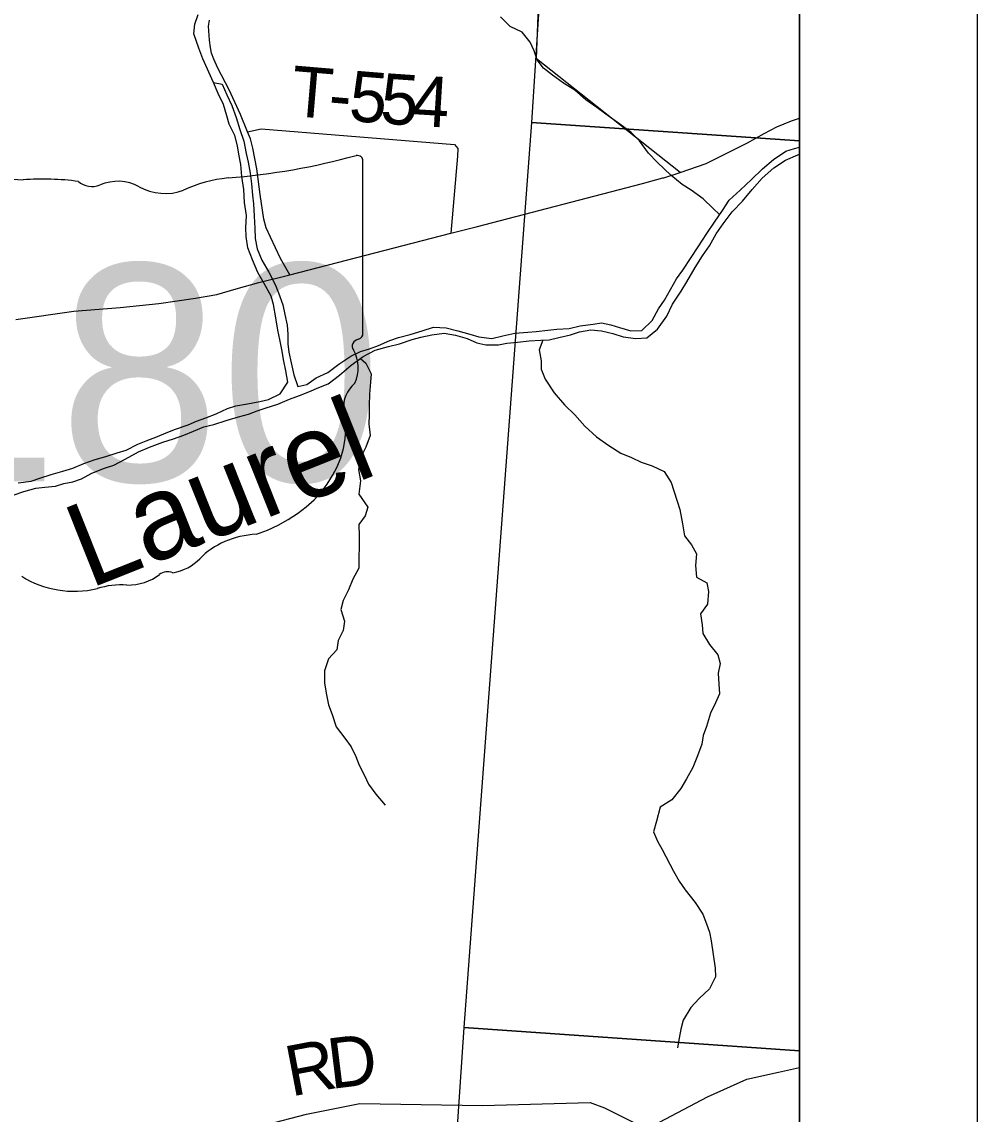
# Model space of a CAD drawing. Extents: x 0 to 42.5, y 0 to 22.
# Drawn here: x 8.462 to 9, y 16.014 to 16.629 of the extents above; entities that cross this region are included whole.
import ezdxf

# ---------------------------------------------------------------- set-up
doc = ezdxf.new("R2010")
doc.units = 0
for name, color, linetype in [('GM_X_County_Road', 7, 'Continuous'), ('GM_X_County_Road_Text', 7, 'Continuous'), ('GM_X_Interchange_Ramps', 7, 'Continuous'), ('GM_X_Minor_River', 7, 'Continuous'), ('GM_X_Minor_River_Text', 7, 'Continuous'), ('GM_X_State_Location', 7, 'Continuous'), ('GM_X_State_Route', 7, 'Continuous'), ('GM_X_State_Shield', 7, 'Continuous'), ('GM_X_Township_Road', 7, 'Continuous'), ('GM_X_Township_Road_Text', 7, 'Continuous'), ('GM_X_Unincorporated', 7, 'Continuous'), ('SH_Cut_Line', 7, 'Continuous'), ('SH_Data', 7, 'Continuous')]:
    doc.layers.add(name, color=color, linetype=linetype)

msp = doc.modelspace()

# ---------------------------------------------------------------- linework, layer by layer
at = {"layer": 'GM_X_County_Road'}
for points in [[(8.82122, 16.00948), (8.84828, 16.02374), (8.87043, 16.03379), (8.88825, 16.03773), (8.9, 16.04036)], [(8.59942, 16.00794), (8.62254, 16.01401), (8.65251, 16.01994), (8.72145, 16.01896), (8.78221, 16.02057), (8.79021, 16.01759), (8.80679, 16.00936)]]:
    msp.add_lwpolyline(points, dxfattribs=at)
at = {"layer": 'GM_X_Interchange_Ramps'}
msp.add_lwpolyline([(8.9, 15.53758), (8.9, 19.05381), (8.80207, 19.06082), (8.79715, 19.06117), (8.45529, 19.08562), (8.42249, 18.59682), (8.4216, 18.58362), (8.41233, 18.47844), (8.38323, 18.14846), (8.33786, 17.63394), (8.30797, 17.29222), (8.30866, 17.28459), (8.30841, 17.27648), (8.30737, 17.26941), (8.29023, 17.08765), (8.28773, 17.0646), (8.28228, 16.99116), (8.27401, 16.89234), (8.25723, 16.70556), (8.24802, 16.59431), (8.24781, 16.59008), (8.17933, 15.79111)], dxfattribs=at)
at = {"layer": 'GM_X_Minor_River'}
for p, q in [((8.5595, 16.62791), (8.56143, 16.63339)), ((8.7371, 16.62657), (8.73165, 16.6321)), ((8.55908, 16.62241), (8.5595, 16.62791)), ((8.74389, 16.62349), (8.7371, 16.62657)), ((8.56186, 16.61443), (8.55908, 16.62241)), ((8.74839, 16.61777), (8.74389, 16.62349)), ((8.56409, 16.60834), (8.56186, 16.61443)), ((8.75063, 16.61301), (8.74839, 16.61777)), ((8.7523, 16.60788), (8.75063, 16.61301)), ((8.57005, 16.59503), (8.56409, 16.60834)), ((8.75586, 16.60312), (8.7523, 16.60788)), ((8.76095, 16.59929), (8.75586, 16.60312)), ((8.76716, 16.5947), (8.76095, 16.59929)), ((8.77357, 16.59068), (8.76716, 16.5947)), ((8.77978, 16.58533), (8.77357, 16.59068)), ((8.78581, 16.58093), (8.77978, 16.58533)), ((8.79089, 16.57729), (8.78581, 16.58093)), ((8.7988, 16.57155), (8.79089, 16.57729)), ((8.80521, 16.56696), (8.7988, 16.57155)), ((8.80991, 16.56219), (8.80521, 16.56696)), ((8.81497, 16.55533), (8.80991, 16.56219)), ((8.82004, 16.54998), (8.81497, 16.55533)), ((8.82757, 16.54292), (8.82004, 16.54998)), ((8.83396, 16.53757), (8.82757, 16.54292)), ((8.83905, 16.5345), (8.83396, 16.53757)), ((8.84584, 16.52952), (8.83905, 16.5345)), ((8.85148, 16.52418), (8.84584, 16.52952)), ((8.85504, 16.52069), (8.85148, 16.52418)), ((8.75555, 16.44994), (8.75339, 16.44459)), ((8.75339, 16.44459), (8.75448, 16.43833)), ((8.6529, 16.43963), (8.65582, 16.43707)), ((8.65582, 16.43707), (8.6588, 16.43098)), ((8.75448, 16.43833), (8.75463, 16.43359)), ((8.6588, 16.43098), (8.65839, 16.42625)), ((8.75463, 16.43359), (8.75686, 16.42807)), ((8.75686, 16.42807), (8.76192, 16.42027)), ((8.65839, 16.42625), (8.65796, 16.41961)), ((8.65796, 16.41961), (8.65773, 16.41316)), ((8.76192, 16.42027), (8.76774, 16.41359)), ((8.65773, 16.41316), (8.65769, 16.40785)), ((8.76774, 16.41359), (8.77357, 16.40786)), ((8.65769, 16.40785), (8.65746, 16.40274)), ((8.77357, 16.40786), (8.7792, 16.40157)), ((8.65746, 16.40274), (8.65836, 16.39628)), ((8.7792, 16.40157), (8.78579, 16.39546)), ((8.65836, 16.39628), (8.65585, 16.38966)), ((8.78579, 16.39546), (8.79257, 16.39067)), ((8.79257, 16.39067), (8.79935, 16.38627)), ((8.65585, 16.38966), (8.65278, 16.38361)), ((8.79935, 16.38627), (8.80539, 16.38395)), ((8.65278, 16.38361), (8.65179, 16.37717)), ((8.80539, 16.38395), (8.81087, 16.38126)), ((8.81087, 16.38126), (8.8171, 16.37914)), ((8.8171, 16.37914), (8.82389, 16.37606)), ((8.65179, 16.37717), (8.65287, 16.37072)), ((8.82389, 16.37606), (8.82782, 16.36977)), ((8.65287, 16.37072), (8.65187, 16.36314)), ((8.82782, 16.36977), (8.8293, 16.36502)), ((8.65187, 16.36314), (8.65693, 16.3559)), ((8.8293, 16.36502), (8.83116, 16.35932)), ((8.65693, 16.3559), (8.65557, 16.35098)), ((8.83116, 16.35932), (8.83264, 16.35457)), ((8.83264, 16.35457), (8.83409, 16.34641)), ((8.65557, 16.35098), (8.65194, 16.34607)), ((8.65194, 16.34607), (8.65208, 16.33962)), ((8.83409, 16.34641), (8.83518, 16.33976)), ((8.65208, 16.33962), (8.65195, 16.3216)), ((8.83518, 16.33976), (8.83912, 16.33462)), ((8.83912, 16.33462), (8.84192, 16.32967)), ((8.84192, 16.32967), (8.8415, 16.32303)), ((8.8415, 16.32303), (8.84202, 16.31639)), ((8.65195, 16.3216), (8.6485, 16.31537)), ((8.6485, 16.31537), (8.64618, 16.30932)), ((8.84202, 16.31639), (8.84786, 16.31332)), ((8.84786, 16.31332), (8.84878, 16.30838)), ((8.64618, 16.30932), (8.64311, 16.30327)), ((8.84878, 16.30838), (8.84816, 16.30118)), ((8.64311, 16.30327), (8.64175, 16.29816)), ((8.84816, 16.30118), (8.84433, 16.2959)), ((8.64175, 16.29816), (8.64378, 16.29169)), ((8.84433, 16.2959), (8.84523, 16.28963)), ((8.64318, 16.28639), (8.64029, 16.28072)), ((8.64378, 16.29169), (8.64318, 16.28639)), ((8.84523, 16.28963), (8.84557, 16.2847)), ((8.64029, 16.28072), (8.6395, 16.2756)), ((8.84557, 16.2847), (8.84932, 16.2786)), ((8.6395, 16.2756), (8.63492, 16.27051)), ((8.84932, 16.2786), (8.85401, 16.2727)), ((8.63492, 16.27051), (8.6326, 16.2637)), ((8.85401, 16.2727), (8.8553, 16.26776)), ((8.8553, 16.26776), (8.85412, 16.26246)), ((8.6326, 16.2637), (8.63255, 16.25668)), ((8.85412, 16.26246), (8.85464, 16.25619)), ((8.63255, 16.25668), (8.63363, 16.25023)), ((8.85464, 16.25619), (8.85498, 16.25069)), ((8.63363, 16.25023), (8.63492, 16.24453)), ((8.85498, 16.25069), (8.85267, 16.24559)), ((8.63492, 16.24453), (8.63696, 16.23902)), ((8.85267, 16.24559), (8.84998, 16.23991)), ((8.63696, 16.23902), (8.63918, 16.23218)), ((8.84998, 16.23991), (8.84766, 16.23234)), ((8.63918, 16.23218), (8.64406, 16.2257)), ((8.84766, 16.23234), (8.84573, 16.22724)), ((8.64406, 16.2257), (8.64762, 16.22093)), ((8.84573, 16.22724), (8.84493, 16.22231)), ((8.64762, 16.22093), (8.65023, 16.21542)), ((8.84493, 16.22231), (8.84261, 16.21588)), ((8.65023, 16.21542), (8.65209, 16.21066)), ((8.84261, 16.21588), (8.83991, 16.20926)), ((8.65209, 16.21066), (8.65508, 16.20476)), ((8.83991, 16.20926), (8.83646, 16.20283)), ((8.65508, 16.20476), (8.65732, 16.19982)), ((8.83646, 16.20283), (8.8332, 16.19735)), ((8.65732, 16.19982), (8.66144, 16.19429)), ((8.66144, 16.19429), (8.6667, 16.188)), ((8.8332, 16.19735), (8.82804, 16.19113)), ((8.82804, 16.19113), (8.82158, 16.187)), ((8.82158, 16.187), (8.81944, 16.17905)), ((8.81944, 16.17905), (8.81788, 16.17299)), ((8.81788, 16.17299), (8.82011, 16.16785)), ((8.82011, 16.16785), (8.82273, 16.1631)), ((8.82273, 16.1631), (8.82908, 16.15092)), ((8.82908, 16.15092), (8.83225, 16.14521)), ((8.83225, 16.14521), (8.83563, 16.14044)), ((8.83563, 16.14044), (8.84126, 16.1332)), ((8.84126, 16.1332), (8.84556, 16.12673)), ((8.84556, 16.12673), (8.84761, 16.12121)), ((8.84761, 16.12121), (8.84928, 16.11646)), ((8.84928, 16.11646), (8.85019, 16.11171)), ((8.85019, 16.11171), (8.85146, 16.10393)), ((8.85146, 16.10393), (8.85254, 16.09615)), ((8.85254, 16.09615), (8.85269, 16.09141)), ((8.85269, 16.09141), (8.84942, 16.0846)), ((8.84942, 16.0846), (8.84352, 16.07914)), ((8.84352, 16.07914), (8.83875, 16.07405)), ((8.83875, 16.07405), (8.83453, 16.06687)), ((8.83453, 16.06687), (8.83317, 16.06195)), ((8.83317, 16.06195), (8.83218, 16.05683)), ((8.83218, 16.05683), (8.83138, 16.05134))]:
    msp.add_line(p, q, dxfattribs=at)
for points in [[(8.49085, 16.37783), (8.49711, 16.38045), (8.50357, 16.38268), (8.50945, 16.38435), (8.5159, 16.38658), (8.52084, 16.38807), (8.52749, 16.39144), (8.53224, 16.39331), (8.5385, 16.39573), (8.54344, 16.39778), (8.54876, 16.39984), (8.55578, 16.40226), (8.56053, 16.40431), (8.56584, 16.40617), (8.57154, 16.40841), (8.578, 16.41141), (8.58275, 16.41289), (8.58919, 16.41418), (8.59621, 16.41546), (8.60114, 16.41657), (8.6076, 16.41975), (8.612, 16.42636), (8.61091, 16.43262), (8.60944, 16.43908), (8.60872, 16.44382), (8.60744, 16.45028), (8.60634, 16.4556), (8.60526, 16.46262), (8.6038, 16.47003), (8.60251, 16.47478), (8.59858, 16.48182), (8.59503, 16.4881), (8.59205, 16.49514), (8.58945, 16.50198), (8.58855, 16.50843), (8.58821, 16.51318), (8.58864, 16.52019), (8.58755, 16.52759), (8.58723, 16.5348), (8.58614, 16.54221), (8.58544, 16.54885), (8.58434, 16.55473), (8.58362, 16.55948), (8.58214, 16.56518), (8.57897, 16.57165), (8.57768, 16.5764), (8.57565, 16.58267), (8.57266, 16.58894), (8.57005, 16.59503), (8.57497, 16.59424), (8.57758, 16.58815), (8.58037, 16.58207), (8.58279, 16.57542), (8.58501, 16.56857), (8.58724, 16.56211), (8.58851, 16.55509), (8.58961, 16.55015), (8.5907, 16.54407), (8.59142, 16.538), (8.59213, 16.53155), (8.59266, 16.5268), (8.59299, 16.51978), (8.59332, 16.51295), (8.59346, 16.50726), (8.59475, 16.50138), (8.59735, 16.4951), (8.60128, 16.48825), (8.60483, 16.4814), (8.60669, 16.47665), (8.6091, 16.4698), (8.61019, 16.46449), (8.61148, 16.45841), (8.61201, 16.45328), (8.61197, 16.44798), (8.6125, 16.44323), (8.61378, 16.43715), (8.61525, 16.43051), (8.61766, 16.42385), (8.62259, 16.42496), (8.62792, 16.42872), (8.63438, 16.43171), (8.64067, 16.43641), (8.64733, 16.44092), (8.65284, 16.44354), (8.65796, 16.44502), (8.6629, 16.44689), (8.66935, 16.44969), (8.67429, 16.45137), (8.68074, 16.45322), (8.68757, 16.45526), (8.69402, 16.45731), (8.70103, 16.45688), (8.70764, 16.45513), (8.71444, 16.45338), (8.71955, 16.45183), (8.72673, 16.45084), (8.73299, 16.45231), (8.73982, 16.45398), (8.74702, 16.4545), (8.75176, 16.45485), (8.75839, 16.45556)], [(8.75839, 16.45556), (8.76332, 16.4561), (8.77032, 16.45662), (8.77658, 16.4581), (8.78379, 16.459), (8.78853, 16.45973), (8.79382, 16.45856), (8.79873, 16.45701), (8.80497, 16.45526), (8.81122, 16.45541), (8.81713, 16.46106), (8.82058, 16.46767), (8.82403, 16.47258), (8.83074, 16.48449), (8.83437, 16.48939), (8.83897, 16.49657), (8.84299, 16.50261), (8.84778, 16.50998), (8.85218, 16.5164), (8.85658, 16.52301), (8.86041, 16.52886), (8.86651, 16.53451), (8.87299, 16.54054), (8.87909, 16.54638), (8.88538, 16.55165), (8.89223, 16.55634), (8.89716, 16.55783), (8.9, 16.55872)], [(8.48112, 16.36766), (8.48586, 16.36914), (8.49098, 16.37025), (8.49573, 16.37192), (8.50162, 16.37511), (8.50865, 16.37791), (8.51396, 16.37958), (8.52042, 16.38295), (8.52784, 16.38708), (8.5341, 16.38969), (8.54151, 16.39249), (8.54758, 16.39434), (8.55347, 16.39639), (8.55878, 16.39863), (8.56467, 16.40106), (8.57036, 16.40254), (8.57719, 16.40477), (8.58422, 16.40681), (8.58972, 16.4083), (8.59465, 16.41016), (8.59978, 16.41183), (8.60623, 16.41388), (8.61288, 16.41668), (8.61857, 16.41873), (8.6237, 16.42078), (8.6294, 16.42321), (8.63472, 16.42545), (8.641, 16.43015), (8.64767, 16.4358), (8.65433, 16.44069), (8.66117, 16.44424), (8.66857, 16.44647), (8.67483, 16.44795), (8.68186, 16.45037), (8.68679, 16.45166), (8.69304, 16.45295), (8.69987, 16.45385), (8.7063, 16.45286), (8.71291, 16.45092), (8.71838, 16.44842), (8.72349, 16.44725), (8.7305, 16.4474), (8.73524, 16.44832), (8.7413, 16.44885), (8.74774, 16.44956), (8.75437, 16.4499), (8.75911, 16.45006), (8.76442, 16.45154), (8.77106, 16.45301), (8.77618, 16.45469), (8.78244, 16.45578), (8.78849, 16.45518), (8.79492, 16.45362), (8.80078, 16.45187), (8.80777, 16.45088), (8.81402, 16.45122), (8.82012, 16.45611), (8.82528, 16.46347), (8.82855, 16.47028), (8.83334, 16.47764), (8.8366, 16.48274), (8.8412, 16.49087), (8.84541, 16.49748), (8.84924, 16.50314), (8.85308, 16.50994), (8.85709, 16.51542), (8.86207, 16.52221), (8.86798, 16.52824), (8.87333, 16.53485), (8.87906, 16.54126), (8.88554, 16.54709), (8.89219, 16.55141), (8.89903, 16.5544), (8.9, 16.55467)], [(8.46011, 16.36969), (8.4675, 16.37059), (8.47225, 16.37227), (8.4787, 16.37431), (8.48534, 16.37616), (8.49085, 16.37783)], [(8.45779, 16.36288), (8.4633, 16.36474), (8.47013, 16.36659), (8.47505, 16.36713), (8.48112, 16.36766)]]:
    msp.add_lwpolyline(points, dxfattribs=at)
at = {"layer": 'GM_X_State_Route'}
for points in [[(8.82304, 16.5413), (8.82353, 16.54144), (8.8329, 16.54439), (8.84737, 16.54949), (8.87072, 16.56117), (8.88009, 16.56643), (8.88732, 16.57004), (8.89554, 16.57349), (8.9, 16.57491)], [(8.45889, 16.46154), (8.49144, 16.4663), (8.51758, 16.46828), (8.53928, 16.47058), (8.55999, 16.47354), (8.57199, 16.47567), (8.58285, 16.4788), (8.59567, 16.48242), (8.6131, 16.48669), (8.70368, 16.5102), (8.71798, 16.51382), (8.8117, 16.53815), (8.82304, 16.5413)]]:
    msp.add_lwpolyline(points, dxfattribs=at)
at = {"layer": 'GM_X_State_Shield'}
for p, q in [((8.65421, 16.45373), (8.65421, 16.55086)), ((8.65418, 16.45375), (8.65421, 16.45373))]:
    msp.add_line(p, q, dxfattribs=at)
for centre, major_axis, start_param, end_param in [((8.54527, 16.79941), (0.32431, 0), 4.814394, 5.042369), ((8.65082, 16.55126), (0.0034, 0), 6.141152, 7.989035), ((8.4623, 16.56782), (0.03436, 0), 4.042523, 4.731795), ((8.47369, 16.44201), (0.12336, 0), 1.404758, 1.657858), ((8.5017, 16.54442), (0.00991, 0), 3.836095, 5.185415), ((8.51625, 16.52296), (0.02061, 0), 0.950623, 2.079405), ((8.58664, 16.48955), (0.06525, 0), 1.699011, 2.107814), ((8.54285, 16.5524), (0.02479, 0), 4.081561, 5.145723), ((8.65058, 16.45335), (0.00364, 0), 5.05454, 6.418171), ((8.65342, 16.4466), (0.00527, 0), 1.883978, 3.671073), ((8.6199, 16.43432), (0.03163, 0), 5.934695, 6.695948), ((8.66641, 16.41308), (0.02301, 0), 2.387724, 3.262537), ((8.56344, 16.40072), (0.08112, 0), 5.101752, 6.440018), ((8.59764, 16.30525), (0.04443, 0), 1.647645, 2.488434), ((8.54136, 16.33938), (0.02621, 0), 4.937069, 5.64225), ((8.49166, 16.34574), (0.0465, 0), 4.026481, 4.996735), ((8.52192, 16.33184), (0.02477, 0), 4.691044, 5.507374), ((8.54433, 16.31386), (0.00698, 0), 1.147584, 2.315152), ((8.51852, 16.28155), (0.03821, 0), 1.495662, 1.94098)]:
    msp.add_ellipse(centre, major_axis=major_axis, ratio=0.8, start_param=start_param, end_param=end_param, dxfattribs=at)
at = {"layer": 'GM_X_Township_Road'}
for points in [[(8.8329, 16.54439), (8.75198, 16.60851), (8.7558, 16.71165), (8.75666, 16.73142), (8.75777, 16.73769), (8.76191, 16.7474), (8.76238, 16.81144), (8.77085, 16.92466), (8.77199, 16.93824), (8.77352, 16.99486), (8.79121, 17.24348), (8.80609, 17.48076), (8.80612, 17.48125)], [(8.6131, 16.48669), (8.60782, 16.49604), (8.6021, 16.508), (8.59966, 16.51331), (8.59851, 16.5182), (8.59636, 16.53199), (8.59449, 16.5465), (8.59233, 16.55814), (8.5909, 16.56345), (8.58917, 16.56733), (8.58529, 16.5771), (8.57897, 16.59089), (8.57251, 16.6031), (8.57021, 16.60828), (8.56906, 16.61158), (8.56834, 16.61474), (8.56791, 16.61891), (8.56734, 16.62681), (8.56777, 16.63011)], [(8.58917, 16.56733), (8.59693, 16.56906), (8.70583, 16.56015), (8.70676, 16.55907)], [(8.70676, 16.55907), (8.70769, 16.55799), (8.70741, 16.55368), (8.70368, 16.5102)]]:
    msp.add_lwpolyline(points, dxfattribs=at)
at = {"layer": 'GM_X_Unincorporated'}
for points in [[(8.9, 16.56221), (8.9, 17.07703), (8.78214, 17.08517), (8.74916, 16.5726)], [(8.9, 16.04975), (8.9, 16.56221), (8.74916, 16.5726), (8.711, 16.06279)], [(8.9, 15.5396), (8.9, 16.04975), (8.711, 16.06279), (8.67682, 15.55582)]]:
    msp.add_lwpolyline(points, close=True, dxfattribs=at)
at = {"layer": 'SH_Cut_Line'}
msp.add_lwpolyline([(8.9, 14.1), (8.9, 19.05381), (8.80207, 19.06082), (8.79715, 19.06117), (8.45529, 19.08562), (8.42249, 18.59682), (8.4216, 18.58362), (8.41233, 18.47844), (8.38323, 18.14846), (8.33786, 17.63394), (8.30797, 17.29222), (8.30866, 17.28459), (8.30841, 17.27648), (8.30737, 17.26941), (8.29023, 17.08765), (8.28773, 17.0646), (8.28228, 16.99116), (8.27401, 16.89234), (8.25723, 16.70556), (8.24802, 16.59431), (8.24781, 16.59008), (8.17933, 15.79111)], dxfattribs=at)
at = {"layer": 'SH_Data'}
for p, q in [((9, 21), (9, 14)), ((8.9, 20.9), (8.9, 14.1))]:
    msp.add_line(p, q, dxfattribs=at)

# ---------------------------------------------------------------- texts
at = {"layer": 'GM_X_County_Road_Text'}
for s, rotation, p in [('D', 7.00438, (8.6362, 16.02814)), ('R', 10.77718, (8.61377, 16.02385))]:
    msp.add_text(s, height=0.02841, rotation=rotation, dxfattribs=at).set_placement(p)
at = {"layer": 'GM_X_Minor_River_Text'}
msp.add_text('Laurel', height=0.047347, rotation=21.72085, dxfattribs=at).set_placement((8.5002, 16.3098))
at = {"layer": 'GM_X_State_Location'}
for s in ['s', 'r']:
    msp.add_text(s, height=0.0000947, dxfattribs=at).set_placement((8.5235, 16.45992))
msp.add_text('180', height=0.0000947, rotation=0.00001, dxfattribs=at).set_placement((8.49007, 16.45303))
at = {"layer": 'GM_X_State_Shield'}
msp.add_text('180', height=0.122327, dxfattribs=at).set_placement((8.39196, 16.37047))
at = {"layer": 'GM_X_Township_Road_Text'}
for s, rotation, p in [('T', 355.13947, (8.613, 16.57637)), ('5', 355.29816, (8.64574, 16.57359)), ('5', 356.02186, (8.66343, 16.57214)), ('4', 356.49067, (8.681, 16.57091)), ('-', 355.14728, (8.63414, 16.57457))]:
    msp.add_text(s, height=0.02841, rotation=rotation, dxfattribs=at).set_placement(p)

doc.saveas('drawing.dxf')
